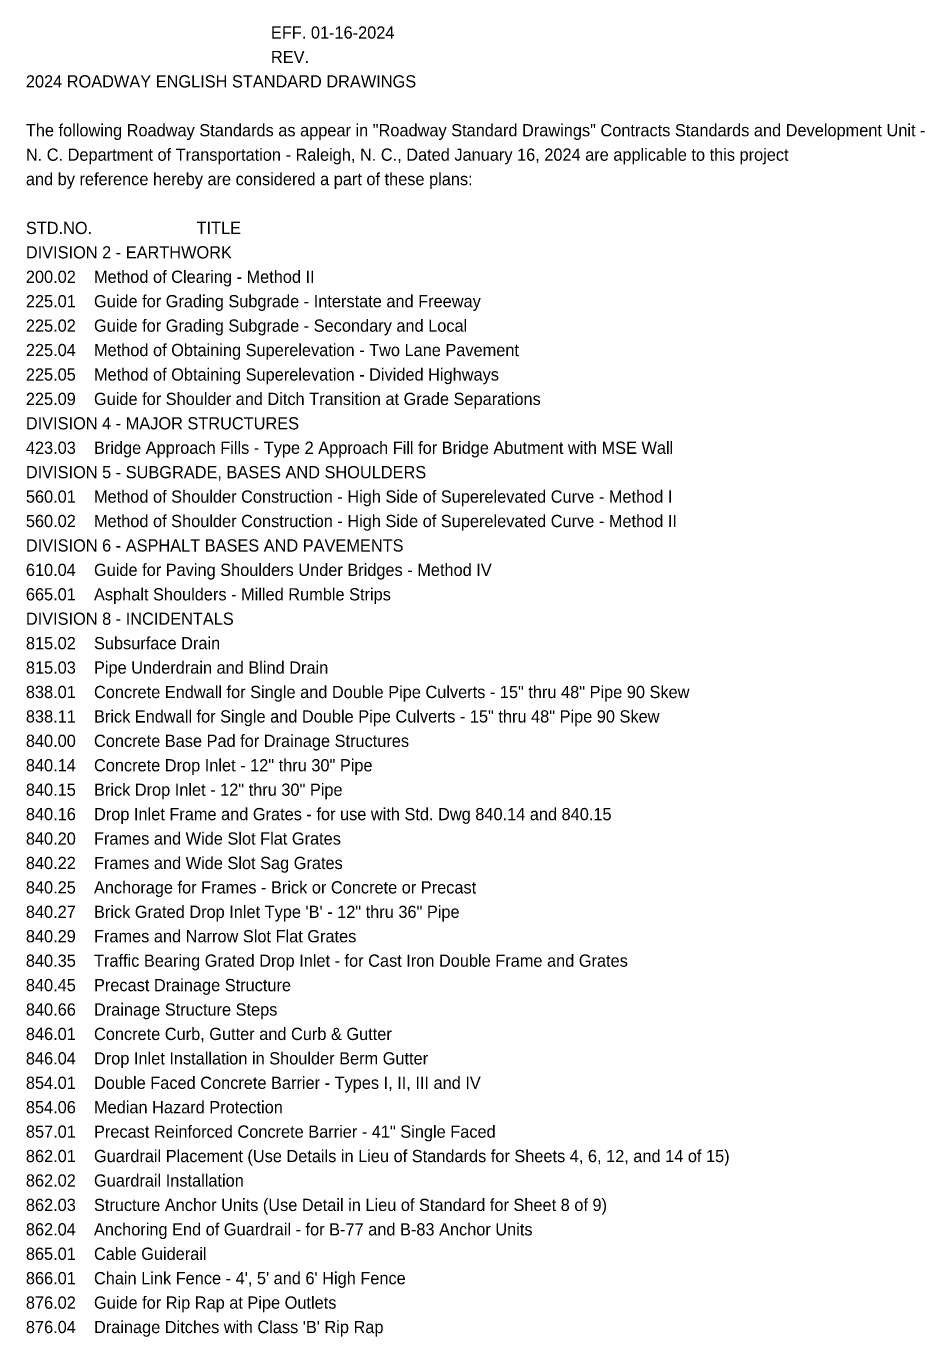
# Model space of a CAD drawing. Extents: x 1844369 to 1844800, y 671424 to 671721.
# Drawn here: x 1844633.57 to 1844661.52, y 671438.3 to 671479.08 of the extents above; entities that cross this region are included whole.
import ezdxf

# ---------------------------------------------------------------- set-up
doc = ezdxf.new("R2010")
doc.units = 0
doc.layers.add('Sheet Data Text CELL', color=7, linetype='Continuous')

msp = doc.modelspace()

# ---------------------------------------------------------------- texts
at = {"layer": 'Sheet Data Text CELL'}
for s, p in [('                                                      EFF. 01-16-2024', (1844633.559, 671478.692)), ('                                                      REV. ', (1844633.559, 671477.932)), ('2024 ROADWAY ENGLISH STANDARD DRAWINGS', (1844633.559, 671477.172)), ('The following Roadway Standards as appear in "Roadway Standard Drawings" Contracts Standards and Development Unit -', (1844633.559, 671475.652)), ('N. C. Department of Transportation - Raleigh, N. C., Dated January 16, 2024 are applicable to this project', (1844633.559, 671474.892)), ('and by reference hereby are considered a part of these plans:', (1844633.559, 671474.132)), ('STD.NO.                       TITLE', (1844633.559, 671472.612)), ('DIVISION 2 - EARTHWORK', (1844633.559, 671471.852)), ('200.02    Method of Clearing - Method II', (1844633.559, 671471.092)), ('225.01    Guide for Grading Subgrade - Interstate and Freeway', (1844633.559, 671470.332)), ('225.02    Guide for Grading Subgrade - Secondary and Local', (1844633.559, 671469.572)), ('225.04    Method of Obtaining Superelevation - Two Lane Pavement', (1844633.559, 671468.812)), ('225.05    Method of Obtaining Superelevation - Divided Highways', (1844633.559, 671468.052)), ('225.09    Guide for Shoulder and Ditch Transition at Grade Separations', (1844633.559, 671467.292)), ('DIVISION 4 - MAJOR STRUCTURES', (1844633.559, 671466.532)), ('423.03    Bridge Approach Fills - Type 2 Approach Fill for Bridge Abutment with MSE Wall', (1844633.559, 671465.772)), ('DIVISION 5 - SUBGRADE, BASES AND SHOULDERS', (1844633.559, 671465.012)), ('560.01    Method of Shoulder Construction - High Side of Superelevated Curve - Method I', (1844633.559, 671464.252)), ('560.02    Method of Shoulder Construction - High Side of Superelevated Curve - Method II', (1844633.559, 671463.492)), ('DIVISION 6 - ASPHALT BASES AND PAVEMENTS', (1844633.559, 671462.732)), ('610.04    Guide for Paving Shoulders Under Bridges - Method IV', (1844633.559, 671461.972)), ('665.01    Asphalt Shoulders - Milled Rumble Strips', (1844633.559, 671461.212)), ('DIVISION 8 - INCIDENTALS', (1844633.559, 671460.452)), ('815.02    Subsurface Drain', (1844633.559, 671459.692)), ('815.03    Pipe Underdrain and Blind Drain', (1844633.559, 671458.932)), ('838.01    Concrete Endwall for Single and Double Pipe Culverts - 15" thru 48" Pipe 90 Skew', (1844633.559, 671458.172)), ('838.11    Brick Endwall for Single and Double Pipe Culverts - 15" thru 48" Pipe 90 Skew', (1844633.559, 671457.412)), ('840.00    Concrete Base Pad for Drainage Structures', (1844633.559, 671456.652)), ('840.14    Concrete Drop Inlet - 12" thru 30" Pipe', (1844633.559, 671455.892)), ('840.15    Brick Drop Inlet - 12" thru 30" Pipe', (1844633.559, 671455.132)), ('840.16    Drop Inlet Frame and Grates - for use with Std. Dwg 840.14 and 840.15', (1844633.559, 671454.372)), ('840.20    Frames and Wide Slot Flat Grates', (1844633.559, 671453.612)), ('840.22    Frames and Wide Slot Sag Grates', (1844633.559, 671452.852)), ('840.25    Anchorage for Frames - Brick or Concrete or Precast', (1844633.559, 671452.092)), ('840.27    Brick Grated Drop Inlet Type \'B\' - 12" thru 36" Pipe', (1844633.559, 671451.332)), ('840.29    Frames and Narrow Slot Flat Grates', (1844633.559, 671450.572)), ('840.35    Traffic Bearing Grated Drop Inlet - for Cast Iron Double Frame and Grates', (1844633.559, 671449.812)), ('840.45    Precast Drainage Structure', (1844633.559, 671449.052)), ('840.66    Drainage Structure Steps', (1844633.559, 671448.292)), ('846.01    Concrete Curb, Gutter and Curb & Gutter', (1844633.559, 671447.532)), ('846.04    Drop Inlet Installation in Shoulder Berm Gutter', (1844633.559, 671446.772)), ('854.01    Double Faced Concrete Barrier - Types I, II, III and IV', (1844633.559, 671446.012)), ('854.06    Median Hazard Protection', (1844633.559, 671445.252)), ('857.01    Precast Reinforced Concrete Barrier - 41" Single Faced', (1844633.559, 671444.492)), ('862.01    Guardrail Placement (Use Details in Lieu of Standards for Sheets 4, 6, 12, and 14 of 15)', (1844633.559, 671443.732)), ('862.02    Guardrail Installation', (1844633.559, 671442.972)), ('862.03    Structure Anchor Units (Use Detail in Lieu of Standard for Sheet 8 of 9)', (1844633.559, 671442.212)), ('862.04    Anchoring End of Guardrail - for B-77 and B-83 Anchor Units', (1844633.559, 671441.452)), ('865.01    Cable Guiderail', (1844633.559, 671440.692)), ("866.01    Chain Link Fence - 4', 5' and 6' High Fence", (1844633.559, 671439.932)), ('876.02    Guide for Rip Rap at Pipe Outlets', (1844633.559, 671439.172)), ("876.04    Drainage Ditches with Class 'B' Rip Rap", (1844633.559, 671438.412))]:
    msp.add_text(s, height=0.38, dxfattribs=at).set_placement(p)

doc.saveas('drawing.dxf')
